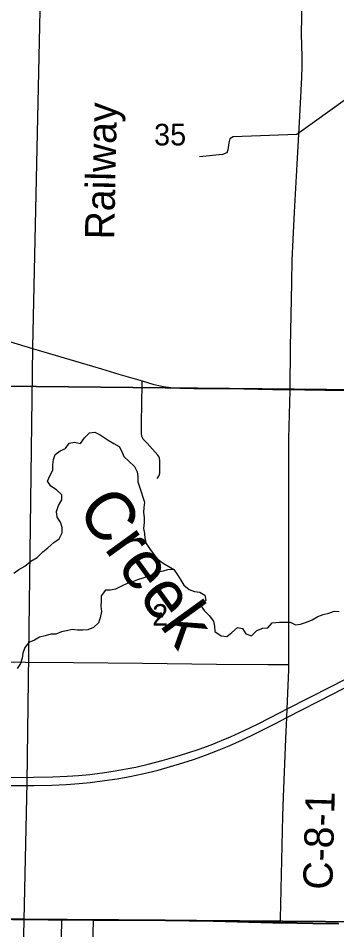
# Model space of a CAD drawing. Extents: x 0 to 42, y 0 to 22.
# Drawn here: x 4.49 to 5.107, y 18.47 to 20.235 of the extents above; entities that cross this region are included whole.
import ezdxf

# ---------------------------------------------------------------- set-up
doc = ezdxf.new("R2010")
doc.units = 0
for name, color, linetype in [('GM_X_Corporation', 7, 'Continuous'), ('GM_X_County_Road', 7, 'Continuous'), ('GM_X_County_Road_Text', 7, 'Continuous'), ('GM_X_Interchange_Ramps', 7, 'Continuous'), ('GM_X_Interstate_Route', 7, 'Continuous'), ('GM_X_Minor_River', 7, 'Continuous'), ('GM_X_Minor_River_Text', 7, 'Continuous'), ('GM_X_Rail_Line', 7, 'Continuous'), ('GM_X_Rail_Line_Text', 7, 'Continuous'), ('GM_X_Section', 7, 'Continuous'), ('GM_X_Section_Text', 7, 'Continuous'), ('GM_X_Township_Road', 7, 'Continuous')]:
    doc.layers.add(name, color=color, linetype=linetype)

msp = doc.modelspace()

# ---------------------------------------------------------------- linework, layer by layer
at = {"layer": 'GM_X_Corporation'}
msp.add_lwpolyline([(4.5728, 18.4172), (4.5741, 18.4897), (4.6347, 18.4893), (4.6294, 18.2409)], dxfattribs=at)
at = {"layer": 'GM_X_County_Road'}
msp.add_line((4.5745, 18.4891), (4.6344, 18.4888), dxfattribs=at)
for points in [[(5.0163, 19.5159), (5.0173, 19.5982), (5.0195, 19.7226), (5.0206, 19.7662), (5.0224, 19.8066), (5.0252, 19.8594), (5.0304, 19.9526), (5.0345, 20.0334), (5.0392, 20.1203), (5.0399, 20.1421), (5.0399, 20.1607), (5.0387, 20.204), (5.0389, 20.2383), (5.0395, 20.3005), (5.0415, 20.4311), (5.0426, 20.5276), (5.0427, 20.5382)], [(4.2757, 19.668), (4.2884, 19.6643), (4.3212, 19.6545), (4.3599, 19.6429), (4.4433, 19.6177), (4.4731, 19.609), (4.5177, 19.5956), (4.634, 19.5613), (4.6512, 19.5561)], [(4.6512, 19.5561), (4.6846, 19.546), (4.7298, 19.5327)], [(4.7298, 19.5327), (4.7503, 19.5267), (4.7623, 19.5236), (4.7715, 19.5218), (4.7808, 19.5204), (4.7901, 19.5195), (4.8026, 19.5189), (4.8306, 19.5183), (4.8803, 19.5179), (4.927, 19.5171), (4.9829, 19.5163), (5.0163, 19.5159)], [(5.0139, 18.9834), (5.0141, 18.9947), (5.0139, 19.0662), (5.014, 19.1502), (5.0138, 19.2342), (5.0138, 19.3867), (5.0142, 19.4209), (5.0163, 19.5142), (5.0163, 19.5159)], [(5.0163, 19.5159), (5.0451, 19.5156), (5.1633, 19.5136), (5.2068, 19.5132), (5.3063, 19.5118), (5.3561, 19.5112), (5.4338, 19.5102), (5.468, 19.51), (5.5768, 19.509), (5.6639, 19.5079), (5.7074, 19.5072), (5.7665, 19.5062), (5.7796, 19.5062)], [(4.9979, 18.4834), (4.9981, 18.4911), (5.0024, 18.6902), (5.0034, 18.7275), (5.0081, 18.8394), (5.0098, 18.8807), (5.0105, 18.8975), (5.0137, 18.973), (5.0139, 18.9834)], [(4.2485, 18.4908), (4.3392, 18.4905), (4.4791, 18.4896), (4.5475, 18.4893), (4.5745, 18.4891)], [(4.6344, 18.4888), (4.6843, 18.4885), (4.7745, 18.4879), (4.8677, 18.4864), (4.9827, 18.4837), (4.9979, 18.4834)], [(4.9979, 18.4834), (5.0604, 18.4821), (5.1106, 18.4815)]]:
    msp.add_lwpolyline(points, dxfattribs=at)
at = {"layer": 'GM_X_Interchange_Ramps'}
for points in [[(5.1104, 18.482), (5.0602, 18.4826), (4.9977, 18.484), (4.9825, 18.4843), (4.8675, 18.4869), (4.7742, 18.4884), (4.6841, 18.489), (4.5473, 18.4899), (4.4789, 18.4901)], [(4.4789, 18.4901), (4.5473, 18.4899), (4.6841, 18.489), (4.7742, 18.4884), (4.8675, 18.4869), (4.9825, 18.4843), (4.9977, 18.484), (5.0602, 18.4826), (5.1104, 18.482)]]:
    msp.add_lwpolyline(points, dxfattribs=at)
at = {"layer": 'GM_X_Interstate_Route'}
for points in [[(4.4138, 18.7644), (4.5195, 18.7654), (4.5569, 18.7662), (4.5848, 18.7673), (4.6066, 18.7688), (4.6283, 18.7709), (4.653, 18.7739), (4.6776, 18.7776), (4.6991, 18.7813), (4.7174, 18.785), (4.7416, 18.7907), (4.7687, 18.7977), (4.7957, 18.8054), (4.8165, 18.8119), (4.8401, 18.8198), (4.8635, 18.8282), (4.8837, 18.8363), (4.9009, 18.8435), (4.9264, 18.8552), (4.9544, 18.8688), (4.9987, 18.8914), (5.0105, 18.8975), (5.0957, 18.9409), (5.1648, 18.9765)], [(4.4369, 18.749), (4.5208, 18.7496), (4.555, 18.7502), (4.5829, 18.7514), (4.6077, 18.7531), (4.6293, 18.7553), (4.6571, 18.7588), (4.6816, 18.7625), (4.7061, 18.7669), (4.7304, 18.772), (4.7606, 18.7793), (4.7846, 18.7858), (4.8084, 18.7929), (4.829, 18.7996), (4.8525, 18.8079), (4.8757, 18.8168), (4.8986, 18.8264), (4.9241, 18.8378), (4.9493, 18.85), (4.9882, 18.8695), (5.0098, 18.8807), (5.0988, 18.9264), (5.2148, 18.9863)]]:
    msp.add_lwpolyline(points, dxfattribs=at)
at = {"layer": 'GM_X_Minor_River'}
for points in [[(5.157, 20.1018), (5.0296, 20.0101), (4.9062, 20.0053), (4.8997, 20.0013), (4.898, 19.9934), (4.8961, 19.9801), (4.8937, 19.9745), (4.8853, 19.9712), (4.8412, 19.9665)], [(4.4814, 19.1607), (4.4911, 19.1673), (4.5026, 19.1739), (4.5142, 19.1839), (4.5265, 19.1908), (4.5374, 19.202), (4.5471, 19.2094), (4.5591, 19.2197), (4.5688, 19.2271), (4.5751, 19.2387), (4.575, 19.2486), (4.5718, 19.2589), (4.5652, 19.2689), (4.5639, 19.28), (4.5676, 19.2913), (4.5743, 19.3025), (4.5746, 19.312), (4.5642, 19.3221), (4.5533, 19.3288), (4.5463, 19.3384), (4.5508, 19.349), (4.5567, 19.3598), (4.5566, 19.3701), (4.5583, 19.3803), (4.5616, 19.3901), (4.5712, 19.3971), (4.5816, 19.4018), (4.5883, 19.4123), (4.599, 19.4139), (4.6103, 19.4114), (4.6181, 19.4222), (4.6278, 19.4319), (4.6381, 19.4332), (4.6486, 19.428), (4.6643, 19.4178), (4.6752, 19.4115), (4.6853, 19.4059), (4.6907, 19.3959), (4.6943, 19.3864), (4.704, 19.3774), (4.7151, 19.3673), (4.7205, 19.3569), (4.7215, 19.3474), (4.7212, 19.3376), (4.7244, 19.3276), (4.728, 19.3177), (4.7311, 19.3077), (4.7343, 19.2982), (4.7333, 19.2876), (4.7323, 19.2777), (4.7336, 19.2682), (4.7338, 19.2583), (4.7324, 19.247), (4.7344, 19.2371), (4.7349, 19.2276), (4.7378, 19.218), (4.7443, 19.208), (4.7513, 19.1983), (4.7591, 19.1883), (4.7706, 19.1801), (4.7815, 19.1734), (4.7912, 19.1678), (4.7982, 19.1574), (4.8047, 19.1467), (4.8106, 19.137), (4.8206, 19.1285), (4.8312, 19.1248), (4.8414, 19.1234), (4.8515, 19.1179), (4.8531, 19.1076), (4.8438, 19.098), (4.85, 19.0879), (4.8597, 19.0786)], [(4.7912, 19.1678), (4.779, 19.1671), (4.7708, 19.1644), (4.7638, 19.1628), (4.7531, 19.1588), (4.7427, 19.1549), (4.7312, 19.151), (4.7209, 19.1474), (4.7113, 19.1434), (4.7006, 19.1406), (4.6899, 19.1352), (4.6784, 19.1294), (4.6688, 19.1273), (4.659, 19.1275), (4.6504, 19.1167), (4.6505, 19.1064), (4.6499, 19.0966), (4.6508, 19.0863), (4.6486, 19.0742), (4.6453, 19.0644), (4.6353, 19.0555), (4.6249, 19.0505), (4.615, 19.0499), (4.6044, 19.0502), (4.5946, 19.0515), (4.5835, 19.0487), (4.5736, 19.0467), (4.5629, 19.0424), (4.553, 19.0422), (4.5419, 19.0394), (4.5312, 19.0366), (4.5212, 19.0308), (4.5101, 19.0261), (4.5027, 19.0164), (4.4986, 19.0055), (4.4973, 18.9956), (4.4944, 18.9854), (4.4877, 18.9757)], [(4.8597, 19.0786), (4.8681, 19.0674), (4.8698, 19.0579), (4.8707, 19.0476), (4.8826, 19.039), (4.894, 19.038), (4.9037, 19.0457), (4.9145, 19.055), (4.9243, 19.0536), (4.9309, 19.0429), (4.9418, 19.0392), (4.9519, 19.0492), (4.9634, 19.0539), (4.9733, 19.0544), (4.9819, 19.0645), (4.9956, 19.0657), (5.007, 19.0655), (5.0164, 19.0656), (5.0266, 19.0601), (5.0368, 19.0618), (5.0483, 19.0653), (5.059, 19.07), (5.0702, 19.0766), (5.0805, 19.0801), (5.0916, 19.0833), (5.1016, 19.0869), (5.1114, 19.0863)]]:
    msp.add_lwpolyline(points, dxfattribs=at)
at = {"layer": 'GM_X_Rail_Line'}
msp.add_lwpolyline([(4.4201, 14.1), (4.4258, 14.4841), (4.4505, 15.4825), (4.4609, 16.2603), (4.4628, 16.4862), (4.4739, 16.927), (4.4741, 16.9438), (4.4795, 17.4845), (4.5072, 18.7551), (4.5183, 19.5978), (4.5387, 20.5461), (4.5449, 20.9)], dxfattribs=at)
at = {"layer": 'GM_X_Section'}
for points in [[(4.2905, 20.5288), (5.2947, 20.5242), (5.2809, 19.5139), (5.2739, 19.514), (4.2741, 19.5242)], [(5.2524, 18.4847), (4.2501, 18.4923), (4.2741, 19.5242), (5.2739, 19.514)], [(4.2501, 18.4923), (5.2524, 18.4847), (5.2334, 17.4797), (4.2338, 17.4876)]]:
    msp.add_lwpolyline(points, close=True, dxfattribs=at)
at = {"layer": 'GM_X_Township_Road'}
for points in [[(4.2757, 19.668), (4.2884, 19.6643), (4.3212, 19.6545), (4.3599, 19.6429), (4.4433, 19.6177), (4.4731, 19.609), (4.5177, 19.5956), (4.634, 19.5613), (4.6512, 19.5561)], [(4.6512, 19.5561), (4.6846, 19.546), (4.7298, 19.5327)], [(4.7588, 19.3436), (4.7611, 19.3463), (4.7628, 19.3494), (4.7634, 19.3508), (4.7637, 19.3522), (4.764, 19.354), (4.764, 19.3578), (4.7639, 19.3612), (4.764, 19.3735), (4.764, 19.3798), (4.7637, 19.3815), (4.7634, 19.3831), (4.7629, 19.3848), (4.7621, 19.3861), (4.7603, 19.3888), (4.7395, 19.4121), (4.7344, 19.4175), (4.7321, 19.4202), (4.7314, 19.4213), (4.7305, 19.4229), (4.7299, 19.4239), (4.7294, 19.4254), (4.7291, 19.4267), (4.7286, 19.4296), (4.7284, 19.4327), (4.7289, 19.4515), (4.7297, 19.5265), (4.7298, 19.5327)], [(4.7298, 19.5327), (4.7503, 19.5267), (4.7623, 19.5236), (4.7715, 19.5218), (4.7808, 19.5204), (4.7901, 19.5195), (4.8026, 19.5189), (4.8306, 19.5183), (4.8803, 19.5179), (4.927, 19.5171), (4.9829, 19.5163), (5.0163, 19.5159)], [(5.0163, 19.5159), (5.0451, 19.5156), (5.1633, 19.5136), (5.2068, 19.5132), (5.3063, 19.5118), (5.3561, 19.5112), (5.4338, 19.5102), (5.468, 19.51), (5.5768, 19.509), (5.6639, 19.5079), (5.7074, 19.5072), (5.7665, 19.5062), (5.7796, 19.5062)], [(4.26, 19.0344), (4.2661, 19.0341), (4.2754, 19.0333), (4.2816, 19.0323), (4.2877, 19.0308), (4.2937, 19.0289), (4.3025, 19.0255), (4.3166, 19.0189), (4.3391, 19.0082), (4.3504, 19.0033), (4.3591, 19), (4.368, 18.9972), (4.3769, 18.9949), (4.386, 18.993), (4.3983, 18.9912), (4.4106, 18.9901), (4.4261, 18.9893), (4.451, 18.9888), (4.504, 18.9884)], [(4.504, 18.9884), (4.5971, 18.9877), (4.7308, 18.9862), (4.8739, 18.9845), (4.9733, 18.9833), (5.0044, 18.9835), (5.0076, 18.9835), (5.0139, 18.9834)]]:
    msp.add_lwpolyline(points, dxfattribs=at)

# ---------------------------------------------------------------- texts
at = {"layer": 'GM_X_County_Road_Text'}
msp.add_text('C-8-1', height=0.05682, rotation=88.5233, dxfattribs=at).set_placement((5.0982, 18.547))
at = {"layer": 'GM_X_Minor_River_Text'}
msp.add_text('Creek', height=0.09476, rotation=305.8588, dxfattribs=at).set_placement((4.6015, 19.2825))
at = {"layer": 'GM_X_Rail_Line_Text'}
msp.add_text('Railway', height=0.05663, rotation=88.7614, dxfattribs=at).set_placement((4.6755, 19.8062))
at = {"layer": 'GM_X_Section_Text'}
for s, height, p in [('35', 0.04186, (4.7529, 19.9887)), ('2', 0.0419, (4.7491, 19.0586))]:
    msp.add_text(s, height=height, rotation=0, dxfattribs=at).set_placement(p)

doc.saveas('drawing.dxf')
